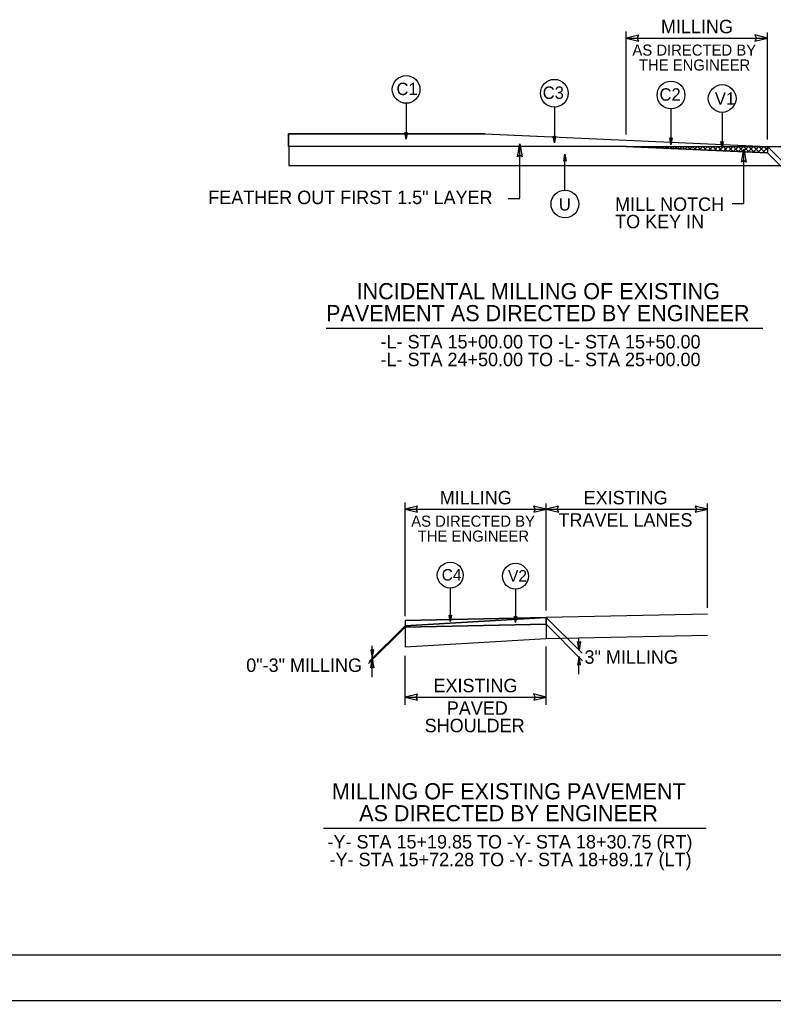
# Model space of a CAD drawing. Extents: x 1553884 to 1554215, y 810431 to 810779.
# Drawn here: x 1553957.4 to 1554013.4, y 810614.4 to 810687.3 of the extents above; entities that cross this region are included whole.
import ezdxf

# ---------------------------------------------------------------- set-up
doc = ezdxf.new("R2010")
doc.units = 0
for name, color, linetype in [('Old_Level_15', 7, 'Continuous'), ('Old_Level_2', 7, 'Continuous'), ('Old_Level_20', 7, 'Continuous'), ('Prop CMT Steel Beam Girder', 7, 'Continuous'), ('Prop EOT', 7, 'Continuous'), ('Prop Hatching', 7, 'Continuous'), ('Prop Lane Arrow CELL', 7, 'Continuous'), ('Prop Shade Light', 7, 'Continuous'), ('Prop Terminator CELL', 7, 'Continuous'), ('Typical Arrow Superelevation CELL', 7, 'Continuous'), ('Typical Detail Pavement Repair CELL', 7, 'Continuous'), ('Typical Pavement Slope Information CELL', 7, 'Continuous'), ('Typical Shoulder Slope CELL', 7, 'Continuous'), ('Typical Text ID Circle CELL', 7, 'Continuous')]:
    doc.layers.add(name, color=color, linetype=linetype)

# ---------------------------------------------------------------- blocks, each defined once
blk = doc.blocks.new('TERMINATOR')
at = {"layer": 'Old_Level_15'}
blk.add_lwpolyline([(-0.187, 0.032), (0, 0), (-0.189, -0.033), (-0.165, 0)], close=True, dxfattribs=at)

msp = doc.modelspace()

# ---------------------------------------------------------------- linework, layer by layer
at = {"layer": 'Old_Level_15'}
for points in [[(1553986.204, 810678.929), (1553986.118, 810678.427), (1553986.029, 810678.932), (1553986.118, 810678.868)], [(1553997.221, 810678.648), (1553997.134, 810678.146), (1553997.045, 810678.651), (1553997.134, 810678.587)], [(1554005.888, 810678.513), (1554005.801, 810678.011), (1554005.712, 810678.516), (1554005.801, 810678.452)], [(1554009.696, 810678.256), (1554009.609, 810677.754), (1554009.52, 810678.259), (1554009.609, 810678.195)], [(1553997.831, 810676.798), (1553997.918, 810677.3), (1553998.007, 810676.795), (1553997.918, 810676.86)], [(1553989.478, 810643.05), (1553989.398, 810642.581), (1553989.314, 810643.052), (1553989.398, 810642.992)], [(1553994.325, 810642.97), (1553994.245, 810642.501), (1553994.161, 810642.972), (1553994.245, 810642.912)], [(1553999.078, 810641.087), (1553998.97, 810640.459), (1553998.858, 810641.09), (1553998.97, 810641.01)], [(1553983.489, 810640.48), (1553983.597, 810639.852), (1553983.709, 810640.484), (1553983.597, 810640.403)], [(1553983.488, 810639.149), (1553983.596, 810639.777), (1553983.707, 810639.146), (1553983.596, 810639.226)], [(1553999.079, 810639.359), (1553998.971, 810639.987), (1553998.86, 810639.356), (1553998.971, 810639.436)]]:
    msp.add_lwpolyline(points, close=True, dxfattribs=at)
at = {"layer": 'Old_Level_2'}
msp.add_line((1553906.821, 810617.805), (1554154.321, 810617.805), dxfattribs=at)
at = {"layer": 'Old_Level_20'}
for p, q in [((1554008.53, 810643.12), (1553996.53, 810642.88)), ((1553996.53, 810642.88), (1553986.037, 810642.274)), ((1553986.037, 810642.274), (1553986.037, 810640.688)), ((1553996.53, 810642.88), (1553996.53, 810641.295)), ((1554008.53, 810641.535), (1553996.53, 810641.295)), ((1553996.53, 810641.295), (1553986.037, 810640.688))]:
    msp.add_line(p, q, dxfattribs=at)
at = {"layer": 'Prop EOT'}
for p, q in [((1553977.388, 810677.885), (1553977.388, 810676.478)), ((1554002.458, 810677.885), (1554016.672, 810677.885)), ((1553977.388, 810676.478), (1554016.672, 810676.478))]:
    msp.add_line(p, q, dxfattribs=at)
at = {"layer": 'Prop Hatching'}
for p, q in [((1554002.479, 810678.764), (1554002.479, 810686.421)), ((1554012.972, 810678.411), (1554012.972, 810686.361)), ((1554002.479, 810685.935), (1554012.972, 810685.935)), ((1553994.573, 810674.021), (1553994.567, 810678.07)), ((1554002.841, 810677.869), (1554002.858, 810677.885)), ((1554002.858, 810677.885), (1554002.875, 810677.867)), ((1554003.204, 810677.852), (1554003.236, 810677.885)), ((1554003.236, 810677.885), (1554003.272, 810677.849)), ((1554003.566, 810677.836), (1554003.615, 810677.885)), ((1554003.615, 810677.885), (1554003.669, 810677.831)), ((1554003.928, 810677.82), (1554003.994, 810677.885)), ((1554003.994, 810677.885), (1554004.066, 810677.813)), ((1554004.291, 810677.803), (1554004.373, 810677.885)), ((1554004.373, 810677.885), (1554004.462, 810677.796)), ((1554004.653, 810677.787), (1554004.752, 810677.885)), ((1554004.752, 810677.885), (1554004.859, 810677.778)), ((1554005.016, 810677.771), (1554005.13, 810677.885)), ((1554005.13, 810677.885), (1554005.256, 810677.76)), ((1554005.378, 810677.754), (1554005.509, 810677.885)), ((1554005.509, 810677.885), (1554005.653, 810677.742)), ((1554005.741, 810677.738), (1554005.888, 810677.885)), ((1554005.888, 810677.885), (1554006.049, 810677.724)), ((1554006.103, 810677.721), (1554006.267, 810677.885)), ((1554006.267, 810677.885), (1554006.446, 810677.706)), ((1554006.465, 810677.705), (1554006.646, 810677.885)), ((1554006.646, 810677.885), (1554006.843, 810677.688)), ((1554006.828, 810677.689), (1554007.024, 810677.885)), ((1554007.024, 810677.885), (1554007.239, 810677.67)), ((1554007.19, 810677.672), (1554007.403, 810677.885)), ((1554007.403, 810677.885), (1554007.636, 810677.652)), ((1554007.553, 810677.656), (1554007.782, 810677.885)), ((1554007.782, 810677.885), (1554008.033, 810677.634)), ((1554007.915, 810677.64), (1554008.161, 810677.885)), ((1554008.161, 810677.885), (1554008.43, 810677.616)), ((1554008.278, 810677.623), (1554008.54, 810677.885)), ((1554008.54, 810677.885), (1554008.826, 810677.598)), ((1554008.64, 810677.607), (1554008.918, 810677.885)), ((1554008.918, 810677.885), (1554009.223, 810677.581)), ((1554009.003, 810677.59), (1554009.297, 810677.885)), ((1554009.297, 810677.885), (1554009.62, 810677.563)), ((1554009.365, 810677.574), (1554009.676, 810677.885)), ((1554009.676, 810677.885), (1554010.017, 810677.545)), ((1554009.727, 810677.558), (1554010.055, 810677.885)), ((1554010.055, 810677.885), (1554010.413, 810677.527)), ((1554010.09, 810677.541), (1554010.434, 810677.885)), ((1554010.434, 810677.885), (1554010.81, 810677.509)), ((1554010.452, 810677.525), (1554010.812, 810677.885)), ((1554010.812, 810677.885), (1554011.207, 810677.491)), ((1554010.815, 810677.509), (1554011.191, 810677.885)), ((1554011.177, 810677.492), (1554011.57, 810677.885)), ((1554011.191, 810677.885), (1554011.603, 810677.473)), ((1554011.217, 810673.635), (1554011.211, 810677.684)), ((1554011.54, 810677.476), (1554011.949, 810677.885)), ((1554011.57, 810677.885), (1554012, 810677.455)), ((1554011.902, 810677.459), (1554012.328, 810677.885)), ((1554011.949, 810677.885), (1554012.397, 810677.437)), ((1554012.264, 810677.443), (1554012.707, 810677.885)), ((1554012.328, 810677.885), (1554012.794, 810677.419)), ((1554012.627, 810677.427), (1554012.972, 810677.772)), ((1554012.707, 810677.885), (1554012.972, 810677.62)), ((1553993.709, 810674.021), (1553994.573, 810674.021)), ((1554010.353, 810673.635), (1554011.217, 810673.635)), ((1553986.037, 810642.992), (1553986.037, 810651.416)), ((1553996.53, 810643.406), (1553996.53, 810651.357)), ((1554008.53, 810643.594), (1554008.53, 810651.357)), ((1553986.037, 810650.931), (1553996.53, 810650.931)), ((1553996.53, 810650.931), (1554008.53, 810650.931)), ((1553996.53, 810636.401), (1553996.53, 810640.733)), ((1553986.037, 810636.401), (1553986.037, 810640.038)), ((1553986.037, 810636.968), (1553996.53, 810636.968))]:
    msp.add_line(p, q, dxfattribs=at)
msp.add_lwpolyline([(1553986.037, 810642.274), (1553996.53, 810642.88), (1553996.53, 810642.38), (1553986.037, 810642.17)], close=True, dxfattribs=at)
at = {"layer": 'Prop Lane Arrow CELL'}
msp.add_line((1553901.353, 810614.43), (1554156.35, 810614.43), dxfattribs=at)
at = {"layer": 'Prop Shade Light'}
for p, q in [((1553991.967, 810678.813), (1553977.385, 810678.814)), ((1553977.385, 810678.814), (1553977.385, 810677.885)), ((1553991.985, 810678.813), (1554002.479, 810678.349)), ((1554002.479, 810678.349), (1554012.972, 810677.885)), ((1554002.469, 810677.885), (1553977.385, 810677.885)), ((1554002.479, 810677.885), (1554012.972, 810677.411)), ((1554012.972, 810677.885), (1554012.972, 810677.411)), ((1553986.037, 810642.67), (1553996.53, 810642.88)), ((1553986.037, 810642.67), (1553986.037, 810642.17)), ((1553986.037, 810642.17), (1553996.53, 810642.38))]:
    msp.add_line(p, q, dxfattribs=at)
at = {"layer": 'Prop Terminator CELL'}
for points in [[(1553977.385, 810678.814), (1553991.967, 810678.813), (1554012.972, 810677.885), (1554012.972, 810677.411), (1554002.479, 810677.885), (1553977.385, 810677.885)], [(1553996.53, 810642.88), (1553986.037, 810642.67), (1553986.037, 810642.17), (1553996.53, 810642.38)]]:
    msp.add_lwpolyline(points, close=True, dxfattribs=at)
at = {"layer": 'Typical Arrow Superelevation CELL'}
for p, q in [((1553980.175, 810664.384), (1554012.624, 810664.384)), ((1553979.974, 810627.226), (1554008.423, 810627.226))]:
    msp.add_line(p, q, dxfattribs=at)
at = {"layer": 'Typical Pavement Slope Information CELL'}
for points in [[(1553994.402, 810677.106), (1553994.567, 810678.07), (1553994.74, 810677.101), (1553994.568, 810677.224)], [(1554011.046, 810676.72), (1554011.211, 810677.684), (1554011.384, 810676.715), (1554011.212, 810676.838)]]:
    msp.add_lwpolyline(points, close=True, dxfattribs=at)
at = {"layer": 'Typical Text ID Circle CELL'}
for p, q in [((1553986.118, 810681.09), (1553986.118, 810678.427)), ((1553997.134, 810680.809), (1553997.134, 810678.146)), ((1554005.801, 810680.674), (1554005.801, 810678.011)), ((1554009.609, 810680.417), (1554009.609, 810677.754)), ((1553997.918, 810674.637), (1553997.918, 810677.3)), ((1554015.633, 810675.225), (1554012.972, 810677.885)), ((1554015.682, 810674.703), (1554012.972, 810677.411)), ((1553989.398, 810645.066), (1553989.398, 810642.581)), ((1553994.245, 810644.986), (1553994.245, 810642.501)), ((1553983.375, 810639.613), (1553986.037, 810642.274)), ((1553999.192, 810640.22), (1553996.53, 810642.88)), ((1553999.24, 810639.672), (1553996.53, 810642.38)), ((1553983.327, 810639.462), (1553986.037, 810642.17)), ((1553998.967, 810640.463), (1553998.967, 810641.373)), ((1553983.6, 810639.857), (1553983.6, 810640.766)), ((1553983.6, 810638.458), (1553983.6, 810639.666)), ((1553998.967, 810638.668), (1553998.967, 810639.876))]:
    msp.add_line(p, q, dxfattribs=at)
for centre, radius in [((1553986.118, 810682.12), 1.03), ((1553997.134, 810681.839), 1.03), ((1554005.801, 810681.704), 1.03), ((1554009.609, 810681.447), 1.03), ((1553997.918, 810673.607), 1.03), ((1553989.398, 810646.028), 0.962), ((1553994.245, 810645.948), 0.962)]:
    msp.add_circle(centre, radius, dxfattribs=at)

# ---------------------------------------------------------------- block references
at = {"layer": 'Prop EOT', "xscale": 4.94508743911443, "yscale": -7.097743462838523}
for p, rotation in [((1554002.479, 810685.935), -179.99768562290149), ((1554012.972, 810685.935), 0.0023143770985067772), ((1553986.037, 810650.931), -179.99768562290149), ((1553996.53, 810650.931), 0.0023143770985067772), ((1553996.53, 810650.931), -179.99768562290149), ((1554008.53, 810650.931), 0.0023143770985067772), ((1553986.037, 810636.968), -179.99768562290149), ((1553996.53, 810636.968), 0.0023143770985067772)]:
    msp.add_blockref('TERMINATOR', p, dxfattribs=dict(at, rotation=rotation))

# ---------------------------------------------------------------- texts
at = {"layer": 'Prop CMT Steel Beam Girder'}
for s, p in [('-L- STA 15+00.00 TO -L- STA 15+50.00', (1553984.217, 810662.875)), ('-L- STA 24+50.00 TO -L- STA 25+00.00', (1553984.217, 810661.557)), ('-Y- STA 15+19.85 TO -Y- STA 18+30.75 (RT)', (1553980.274, 810625.717)), ('-Y- STA 15+72.28 TO -Y- STA 18+89.17 (LT)', (1553980.43, 810624.399))]:
    msp.add_text(s, height=1, dxfattribs=at).set_placement(p)
at = {"layer": 'Prop EOT'}
for s, height, p in [('MILLING', 1, (1554005.06, 810686.293)), ('AS DIRECTED BY', 0.825, (1554002.938, 810684.632)), ('THE ENGINEER', 0.825, (1554003.422, 810683.523)), ('FEATHER OUT FIRST 1.5" LAYER', 1, (1553971.411, 810673.598)), ('MILL NOTCH', 1, (1554001.654, 810673.091)), ('TO KEY IN', 1, (1554001.654, 810671.807)), ('MILLING', 1, (1553988.618, 810651.289)), ('EXISTING', 1, (1553999.313, 810651.289)), ('AS DIRECTED BY', 0.825, (1553986.496, 810649.627)), ('TRAVEL LANES', 1, (1553997.441, 810649.629)), ('THE ENGINEER', 0.825, (1553986.98, 810648.518)), ('EXISTING', 1, (1553988.152, 810637.326)), ('PAVED', 1, (1553989.141, 810635.65)), ('SHOULDER', 1, (1553987.496, 810634.356))]:
    msp.add_text(s, height=height, rotation=0.00231, dxfattribs=at).set_placement(p)
for s, p in [('3" MILLING', (1553999.376, 810639.444)), ('0"-3" MILLING', (1553974.232, 810638.837))]:
    msp.add_text(s, height=1, dxfattribs=at).set_placement(p)
at = {"layer": 'Typical Detail Pavement Repair CELL'}
for s, height, p in [('C1', 0.9223, (1553985.402, 810681.702)), ('C3', 0.9223, (1553996.269, 810681.42)), ('C2', 0.9223, (1554004.951, 810681.285)), ('V1', 0.9223, (1554009.068, 810680.986)), ('C4', 0.8608, (1553988.762, 810645.621)), ('V2', 0.8608, (1553993.693, 810645.542))]:
    msp.add_text(s, height=height, dxfattribs=at).set_placement(p)
msp.add_text('U', height=0.922, rotation=360, dxfattribs=at).set_placement((1553997.47, 810673.117))
at = {"layer": 'Typical Shoulder Slope CELL'}
for s, p in [('INCIDENTAL MILLING OF EXISTING', (1553982.432, 810666.527)), ('PAVEMENT AS DIRECTED BY ENGINEER', (1553980.166, 810664.898)), ('MILLING OF EXISTING PAVEMENT', (1553980.598, 810629.369)), ('AS DIRECTED BY ENGINEER', (1553982.625, 810627.74))]:
    msp.add_text(s, height=1.2, dxfattribs=at).set_placement(p)

doc.saveas('drawing.dxf')
